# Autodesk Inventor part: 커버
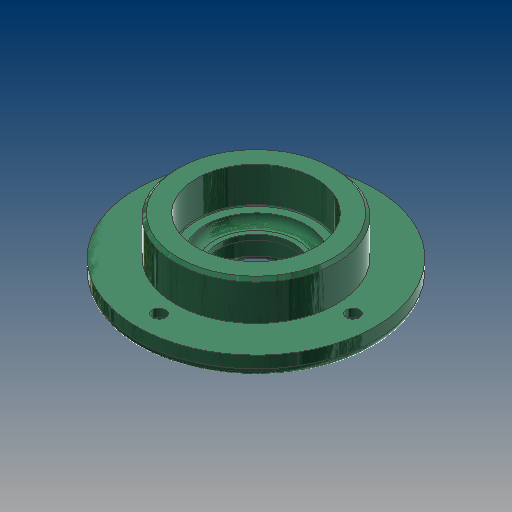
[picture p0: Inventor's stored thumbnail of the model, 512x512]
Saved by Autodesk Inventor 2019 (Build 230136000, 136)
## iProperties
Company: 한국ATC센터
Created: 2014-10
Part Number: 커버
Document SubType Name: Modeling
Designer: KYOUNG IL JANG
Density: 2.71 g/cm^3
Mass: 121.214 g
Surface Area: 161.165 cm^2
Volume: 44.7286 cm^3
Material: 알루미늄 6061
Appearance: 알루미늄 - 평지
Author: KYOUNG IL JANG
Revision Number: 1
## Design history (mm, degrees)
sketch "스케치1"
  geometry: C1 r 40 at (0, 0); 1 further point
  constraints: 1 centre point, 1 coincident
  dimensions: "d0" = 80 diameter of C1
extrude "돌출1" new body sketch "스케치1" distance "d1" = 7; taper "d2" = 0 deg
sketch "스케치2"
  geometry: C1 r 27 at (0, 0); 1 further point
  constraints: 1 centre point, 1 coincident
  dimensions: "d3" = 54 diameter of C1
extrude "돌출2" join sketch "스케치2" distance "d4" = 13; taper "d5" = 0 deg
sketch "스케치3"
  geometry: C1 r 20 at (0, 0); 1 further point
  constraints: 1 centre point, 1 coincident
  dimensions: "d6" = 40 diameter of C1
extrude "돌출3" join sketch "스케치3" distance "d7" = 5; taper "d8" = 0 deg
hole "구멍1" diameter "d11" = 25; stored, may be unused: countersink angle "d15" = 90 deg, drill point angle "d17" = 118 deg; dims "d9" = 10, "d10" = 10, "d12" = 6, "d13" = 32, "d14" = 8.3, "d16" = 8
hole "구멍2" diameter "d20" = 34; stored, may be unused: countersink angle "d24" = 90 deg, drill point angle "d26" = 0 deg; dims "d18" = 10, "d19" = 10, "d21" = 6, "d22" = 40, "d23" = 12, "d25" = 3
fillet "모깎기2" dims "d34" = 3
fillet "모깎기1" dims "d27" = 0.3
chamfer "모따기1" distance "d28" = 1; stored, may be unused: second distance "d29" = 2, angle "d30" = 45 deg
chamfer "모따기2" distance "d31" = 1.2; stored, may be unused: second distance "d32" = 2, angle "d33" = 30 deg
sketch "스케치4" dims "d35" = 65
  geometry: 3 further points
  constraints: 2 horizontal alignment, 1 coincident, 2 other
hole "구멍3" sketch "스케치4" at (32.5, 0) diameter "d36" = 4.5; stored, may be unused: countersink angle "d40" = 90 deg, drill point angle "d42" = 118 deg; dims "d37" = 6, "d38" = 8, "d39" = 4.4, "d41" = 13
node "솔리드1"
pattern_circular "원형 패턴1" dims angle "d44" = 360 deg
